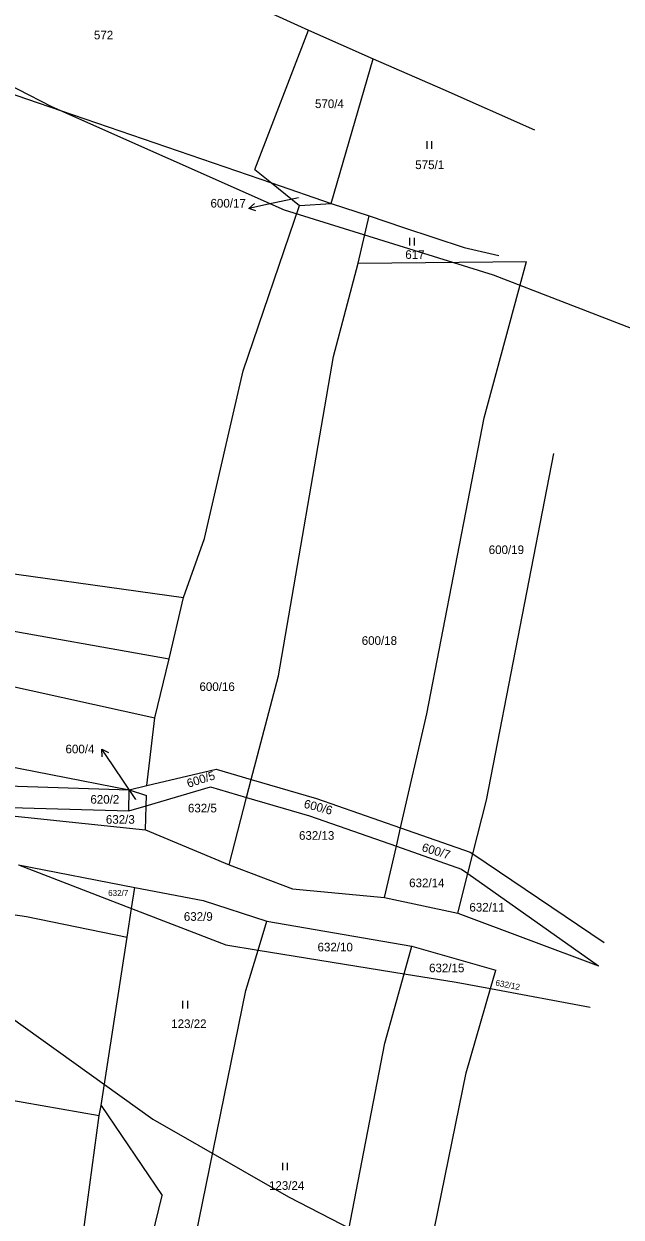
# Model space of a CAD drawing. Extents: x -743888 to -742027, y -1128394 to -1126768.
# Drawn here: x -742597.9 to -742480.3, y -1127325 to -1127090.1 of the extents above; entities that cross this region are included whole.
import ezdxf

# ---------------------------------------------------------------- set-up
doc = ezdxf.new("R2010")
doc.units = 0
for name, color, linetype in [('Vrstva 1', 7, 'Continuous'), ('Vrstva 16', 7, 'Continuous'), ('Vrstva 18', 7, 'Continuous'), ('Vrstva 25', 7, 'Continuous'), ('Vrstva 52', 7, 'Continuous'), ('Vrstva 6', 7, 'Continuous')]:
    doc.layers.add(name, color=color, linetype=linetype)

msp = doc.modelspace()

# ---------------------------------------------------------------- linework, layer by layer
at = {"layer": 'Vrstva 1'}
for points in [[(-742603.37, -1127102.87), (-742595.15, -1127105.68)], [(-742595.15, -1127105.68), (-742549.17, -1127121.43)], [(-742549.17, -1127121.43), (-742537.43, -1127125.45)], [(-742537.43, -1127125.45), (-742529.93, -1127127.94)], [(-742529.93, -1127127.94), (-742523.19, -1127130.18)], [(-742523.19, -1127130.18), (-742511.23, -1127134.16)], [(-742511.23, -1127134.16), (-742504.39, -1127135.7)], [(-742573.72, -1127240.07), (-742560.09, -1127236.86)], [(-742560.09, -1127236.86), (-742553.15, -1127238.87)], [(-742621.26, -1127239.44), (-742577.19, -1127240.89)], [(-742577.26, -1127245.05), (-742577.19, -1127240.89)], [(-742577.19, -1127240.89), (-742573.72, -1127240.07)], [(-742573.86, -1127244.05), (-742561.22, -1127240.32)], [(-742561.22, -1127240.32), (-742554.07, -1127242.4)], [(-742553.15, -1127238.87), (-742540.33, -1127242.59)], [(-742554.07, -1127242.4), (-742541.7, -1127246.01)], [(-742540.33, -1127242.59), (-742523.75, -1127248.38)], [(-742621.56, -1127243.8), (-742577.26, -1127245.05)], [(-742577.26, -1127245.05), (-742573.86, -1127244.05)], [(-742541.7, -1127246.01), (-742524.58, -1127252.01)], [(-742523.75, -1127248.38), (-742510.08, -1127253.15)], [(-742524.58, -1127252.01), (-742511.77, -1127256.49)], [(-742510.08, -1127253.15), (-742509.51, -1127253.53)], [(-742509.51, -1127253.53), (-742483.68, -1127270.99)], [(-742598.97, -1127255.65), (-742576.72, -1127264.27)], [(-742511.77, -1127256.49), (-742510.5, -1127257.39)], [(-742510.5, -1127257.39), (-742484.78, -1127275.57)], [(-742576.72, -1127264.27), (-742558.2, -1127271.45)], [(-742558.2, -1127271.45), (-742551.83, -1127272.48)], [(-742551.83, -1127272.48), (-742523.05, -1127277.11)], [(-742523.05, -1127277.11), (-742512.81, -1127278.76)], [(-742512.81, -1127278.76), (-742506.04, -1127280.03)], [(-742506.04, -1127280.03), (-742486.41, -1127283.7)]]:
    msp.add_lwpolyline(points, dxfattribs=at)
at = {"layer": 'Vrstva 16'}
for p, q in [((-742552.23, -1127126.95), (-742553.66, -1127126.49)), ((-742582.49, -1127234.39), (-742582.59, -1127232.89))]:
    msp.add_line(p, q, dxfattribs=at)
for points in [[(-742549.75, -1127125.64), (-742553.66, -1127126.49), (-742552.55, -1127125.48)], [(-742543.87, -1127124.36), (-742549.75, -1127125.64)], [(-742580.36, -1127236.21), (-742582.59, -1127232.89), (-742581.25, -1127233.55)], [(-742575.92, -1127242.8), (-742580.36, -1127236.21)]]:
    msp.add_lwpolyline(points, dxfattribs=at)
at = {"layer": 'Vrstva 25'}
for p, q in [((-742518.61, -1127113.23), (-742518.61, -1127114.73)), ((-742517.61, -1127114.73), (-742517.61, -1127113.23)), ((-742522.02, -1127132.26), (-742522.02, -1127133.76)), ((-742521.02, -1127133.76), (-742521.02, -1127132.26)), ((-742566.68, -1127282.43), (-742566.68, -1127283.93)), ((-742565.68, -1127283.93), (-742565.68, -1127282.43)), ((-742547.03, -1127314.3), (-742547.03, -1127315.8)), ((-742546.03, -1127315.8), (-742546.03, -1127314.3))]:
    msp.add_line(p, q, dxfattribs=at)
at = {"layer": 'Vrstva 52'}
for points in [[(-742646.81, -1127076.25), (-742612.44, -1127096.13), (-742592.5, -1127106.38), (-742546.69, -1127126.75), (-742505.56, -1127139.5), (-742478.38, -1127150), (-742453.38, -1127158.5), (-742442.31, -1127163.63), (-742435.56, -1127165.75), (-742424.06, -1127170.88), (-742339.69, -1127206.5), (-742305.31, -1127215.88), (-742247.63, -1127232), (-742239.56, -1127234.88), (-742196.25, -1127246), (-742170.81, -1127254), (-742159.38, -1127257.38), (-742097.81, -1127270.5)], [(-742677.75, -1127229.38), (-742653.19, -1127246), (-742647.76, -1127250.61), (-742638.31, -1127258.63), (-742572.56, -1127305.75), (-742545.81, -1127321), (-742506.38, -1127341.38)]]:
    msp.add_lwpolyline(points, dxfattribs=at)
at = {"layer": 'Vrstva 6'}
for points in [[(-742554.78, -1127085.5), (-742541.89, -1127091.38)], [(-742552.48, -1127118.77), (-742541.89, -1127091.38)], [(-742541.89, -1127091.38), (-742529.16, -1127097)], [(-742537.43, -1127125.45), (-742529.16, -1127097)], [(-742529.16, -1127097), (-742515.45, -1127102.99)], [(-742515.45, -1127102.99), (-742497.42, -1127110.95)], [(-742552.48, -1127118.77), (-742549.17, -1127121.43)], [(-742549.17, -1127121.43), (-742543.65, -1127125.88)], [(-742554.78, -1127158.4), (-742543.65, -1127125.88)], [(-742543.65, -1127125.88), (-742537.43, -1127125.45)], [(-742532.11, -1127137.2), (-742529.93, -1127127.94)], [(-742536.99, -1127155.61), (-742532.11, -1127137.2)], [(-742532.11, -1127137.2), (-742498.96, -1127136.92)], [(-742507.29, -1127167.65), (-742498.96, -1127136.92)], [(-742547.82, -1127218.47), (-742536.99, -1127155.61)], [(-742562.37, -1127191.45), (-742554.78, -1127158.4)], [(-742518.59, -1127225.94), (-742507.29, -1127167.65)], [(-742506.81, -1127242.95), (-742493.61, -1127174.67)], [(-742566.48, -1127203.04), (-742562.37, -1127191.45)], [(-742644.1, -1127192.22), (-742566.48, -1127203.04)], [(-742569.32, -1127215.09), (-742566.48, -1127203.04)], [(-742606.23, -1127208.56), (-742569.32, -1127215.09)], [(-742572.17, -1127226.73), (-742569.32, -1127215.09)], [(-742608.43, -1127218.73), (-742572.17, -1127226.73)], [(-742553.15, -1127238.87), (-742547.82, -1127218.47)], [(-742573.72, -1127240.07), (-742572.17, -1127226.73)], [(-742523.75, -1127248.38), (-742518.59, -1127225.94)], [(-742608.13, -1127234.85), (-742577.19, -1127240.89)], [(-742577.19, -1127240.89), (-742573.79, -1127242.02)], [(-742554.07, -1127242.4), (-742553.15, -1127238.87)], [(-742573.86, -1127244.05), (-742573.79, -1127242.02)], [(-742557.53, -1127255.65), (-742554.07, -1127242.4)], [(-742509.51, -1127253.53), (-742506.81, -1127242.95)], [(-742621.56, -1127243.8), (-742574.02, -1127248.78)], [(-742574.02, -1127248.78), (-742573.86, -1127244.05)], [(-742574.02, -1127248.78), (-742557.53, -1127255.65)], [(-742524.58, -1127252.01), (-742523.75, -1127248.38)], [(-742526.9, -1127262.12), (-742524.58, -1127252.01)], [(-742510.5, -1127257.39), (-742509.51, -1127253.53)], [(-742655.59, -1127257.18), (-742597.39, -1127265.81)], [(-742598.97, -1127255.65), (-742576.08, -1127260.13)], [(-742557.53, -1127255.65), (-742545.05, -1127260.38)], [(-742512.49, -1127265.17), (-742510.5, -1127257.39)], [(-742576.72, -1127264.27), (-742576.08, -1127260.13)], [(-742576.08, -1127260.13), (-742562.63, -1127262.7)], [(-742545.05, -1127260.38), (-742526.9, -1127262.12)], [(-742526.9, -1127262.12), (-742512.49, -1127265.17)], [(-742577.59, -1127269.9), (-742576.72, -1127264.27)], [(-742562.63, -1127262.7), (-742550.1, -1127266.78)], [(-742597.39, -1127265.81), (-742577.59, -1127269.9)], [(-742551.83, -1127272.48), (-742550.1, -1127266.78)], [(-742550.1, -1127266.78), (-742521.55, -1127271.68)], [(-742512.49, -1127265.17), (-742484.78, -1127275.57)], [(-742582.72, -1127303.04), (-742577.59, -1127269.9)], [(-742554.25, -1127280.44), (-742551.83, -1127272.48)], [(-742523.05, -1127277.11), (-742521.55, -1127271.68)], [(-742521.55, -1127271.68), (-742504.98, -1127276.38)], [(-742526.83, -1127290.76), (-742523.05, -1127277.11)], [(-742506.04, -1127280.03), (-742504.98, -1127276.38)], [(-742565.58, -1127336.15), (-742554.25, -1127280.44)], [(-742510.84, -1127296.63), (-742506.04, -1127280.03)], [(-742538.11, -1127348.86), (-742526.83, -1127290.76)], [(-742639.33, -1127295.15), (-742583.12, -1127305.02)], [(-742530.91, -1127395.09), (-742510.84, -1127296.63)], [(-742583.12, -1127305.02), (-742582.72, -1127303.04)], [(-742582.72, -1127303.04), (-742570.71, -1127320.74)], [(-742586.78, -1127332.31), (-742583.12, -1127305.02)], [(-742580.44, -1127360.6), (-742570.71, -1127320.74)]]:
    msp.add_lwpolyline(points, dxfattribs=at)

# ---------------------------------------------------------------- texts
at = {"layer": 'Vrstva 16'}
for s, p in [('600/17', (-742561.19, -1127126.28)), ('600/4', (-742589.74, -1127233.72))]:
    msp.add_text(s, height=1.7, dxfattribs=at).set_placement(p)
at = {"layer": 'Vrstva 18'}
for s, height, p in [('572', 1.7, (-742584.14, -1127093.17)), ('570/4', 1.7, (-742540.61, -1127106.7)), ('575/1', 1.7, (-742520.87, -1127118.71)), ('600/17', 0.1, (-742543.87, -1127124.36)), ('617', 1.7, (-742522.83, -1127136.39)), ('600/19', 1.7, (-742506.4, -1127194.49)), ('600/18', 1.7, (-742531.41, -1127212.37)), ('600/16', 1.7, (-742563.36, -1127221.44)), ('620/2', 1.7, (-742584.84, -1127243.63)), ('600/4', 0.1, (-742575.92, -1127242.8)), ('632/5', 1.7, (-742565.63, -1127245.35)), ('632/3', 1.7, (-742581.79, -1127247.58)), ('632/13', 1.7, (-742543.76, -1127250.74)), ('632/14', 1.7, (-742522.07, -1127260.07)), ('632/7', 1.19, (-742581.35, -1127261.8)), ('632/11', 1.7, (-742510.21, -1127264.87)), ('632/9', 1.7, (-742566.44, -1127266.69)), ('632/10', 1.7, (-742540.11, -1127272.71)), ('632/15', 1.7, (-742518.15, -1127276.82)), ('123/22', 1.7, (-742568.92, -1127287.8)), ('123/24', 1.7, (-742549.67, -1127319.65))]:
    msp.add_text(s, height=height, dxfattribs=at).set_placement(p)
for s, height, rotation, p in [('600/5', 1.7, 17.9562, (-742565.53, -1127240.52)), ('600/6', 1.7, 345.3735, (-742542.94, -1127244.4)), ('600/7', 1.7, 343.1148, (-742519.72, -1127252.94)), ('632/12', 1.19, 348.9379, (-742505.16, -1127279.42))]:
    msp.add_text(s, height=height, rotation=rotation, dxfattribs=at).set_placement(p)

doc.saveas('drawing.dxf')
